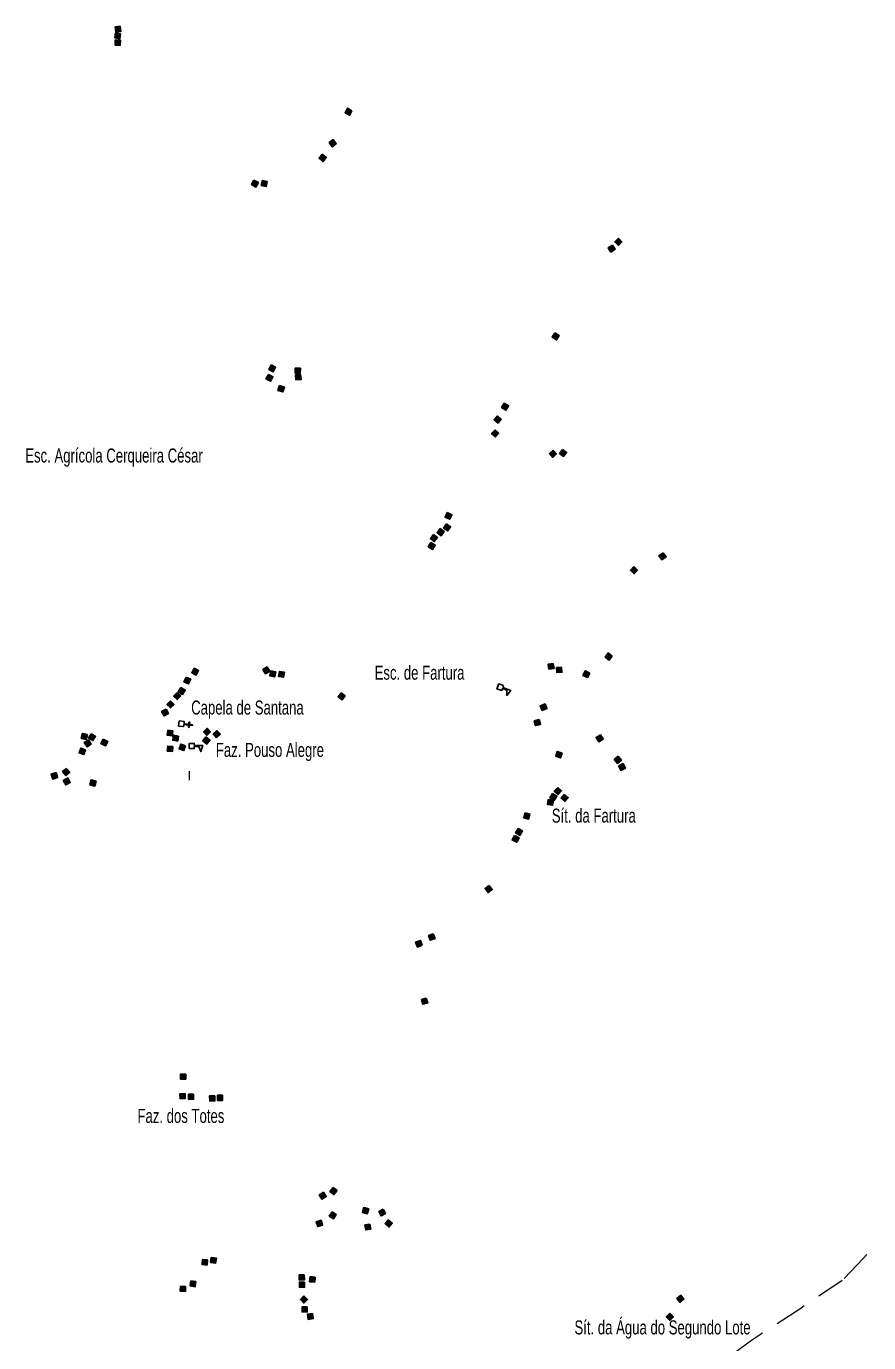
# Model space of a CAD drawing. Extents: x 679 to 705, y 7427.4 to 7455.4.
# Drawn here: x 688.04 to 692.84, y 7440 to 7447.5 of the extents above; entities that cross this region are included whole.
import ezdxf

# ---------------------------------------------------------------- set-up
doc = ezdxf.new("R2010")
doc.units = 0
doc.header["$LTSCALE"] = 0.032
doc.linetypes.add('DOT_DASHED', pattern=[7.7, 5, -1.2, 0.3, -1.2])
for name, color, linetype, lineweight in [('2', 7, 'Continuous', 25), ('4', 7, 'Continuous', 25), ('51', 7, 'Continuous', 13), ('56', 7, 'DOT_DASHED', 13), ('6', 7, 'Continuous', 25)]:
    doc.layers.add(name, color=color, linetype=linetype, lineweight=lineweight)
doc.layers.add('61', color=7, linetype='Continuous')

msp = doc.modelspace()

# ---------------------------------------------------------------- hatches: boundary and pattern name
at = {"layer": '2'}
for points in [[(688.5726, 7447.4971), (688.5764, 7447.4684), (688.5477, 7447.4646), (688.5438, 7447.4933)], [(688.5749, 7447.455), (688.5705, 7447.4263), (688.5418, 7447.4307), (688.5462, 7447.4594)], [(688.5734, 7447.4184), (688.5724, 7447.3894), (688.5434, 7447.3905), (688.5445, 7447.4195)], [(689.8928, 7447.0163), (689.8789, 7446.9909), (689.8535, 7447.0048), (689.8674, 7447.0302)], [(689.7627, 7446.8349), (689.7863, 7446.8517), (689.8031, 7446.828), (689.7795, 7446.8112)], [(689.7233, 7446.7681), (689.7462, 7446.7503), (689.7284, 7446.7274), (689.7055, 7446.7452)], [(689.3344, 7446.6207), (689.3599, 7446.6068), (689.346, 7446.5813), (689.3205, 7446.5952)], [(689.4106, 7446.6128), (689.4042, 7446.5845), (689.3759, 7446.5908), (689.3823, 7446.6191)], [(691.4108, 7446.2897), (691.4313, 7446.2692), (691.4108, 7446.2487), (691.3903, 7446.2692)], [(691.3764, 7446.2511), (691.3924, 7446.2269), (691.3682, 7446.2109), (691.3522, 7446.2351)], [(691.0483, 7445.751), (691.0733, 7445.7363), (691.0585, 7445.7113), (691.0336, 7445.726)], [(689.432, 7445.5688), (689.4578, 7445.5556), (689.4445, 7445.5297), (689.4187, 7445.543)], [(689.5989, 7445.5494), (689.5977, 7445.5204), (689.5688, 7445.5216), (689.57, 7445.5506)], [(689.4166, 7445.5147), (689.442, 7445.5007), (689.4279, 7445.4753), (689.4026, 7445.4893)], [(689.6004, 7445.5143), (689.6028, 7445.4854), (689.5738, 7445.4831), (689.5715, 7445.512)], [(689.4799, 7445.4509), (689.5076, 7445.4424), (689.4991, 7445.4147), (689.4714, 7445.4232)], [(690.7599, 7445.3504), (690.7849, 7445.3356), (690.7701, 7445.3106), (690.7452, 7445.3254)], [(690.7219, 7445.2776), (690.7438, 7445.2586), (690.7249, 7445.2367), (690.7029, 7445.2556)], [(690.7078, 7445.1994), (690.7295, 7445.1801), (690.7102, 7445.1585), (690.6885, 7445.1778)], [(691.0387, 7445.083), (691.0585, 7445.0618), (691.0372, 7445.042), (691.0175, 7445.0633)], [(691.0928, 7445.0876), (691.1159, 7445.0701), (691.0984, 7445.0469), (691.0753, 7445.0644)], [(690.4361, 7444.7276), (690.4623, 7444.7152), (690.45, 7444.689), (690.4237, 7444.7013)], [(690.4309, 7444.663), (690.455, 7444.6469), (690.4389, 7444.6227), (690.4148, 7444.6388)], [(690.3576, 7444.6026), (690.3802, 7444.5845), (690.3621, 7444.5619), (690.3395, 7444.58)], [(690.3952, 7444.636), (690.4185, 7444.6187), (690.4011, 7444.5955), (690.3779, 7444.6128)], [(690.3422, 7444.5574), (690.3671, 7444.5426), (690.3523, 7444.5177), (690.3274, 7444.5325)], [(691.6655, 7444.4981), (691.6824, 7444.4745), (691.6588, 7444.4576), (691.6419, 7444.4812)], [(691.4993, 7444.4201), (691.5202, 7444.4), (691.5001, 7444.3791), (691.4792, 7444.3992)], [(691.3761, 7443.9102), (691.3587, 7443.887), (691.3355, 7443.9044), (691.3529, 7443.9276)], [(688.9934, 7443.841), (689.0191, 7443.8275), (689.0055, 7443.8018), (688.9799, 7443.8154)], [(689.4102, 7443.8495), (689.4254, 7443.8248), (689.4007, 7443.8096), (689.3855, 7443.8343)], [(689.4304, 7443.826), (689.4587, 7443.8197), (689.4525, 7443.7914), (689.4241, 7443.7977)], [(689.5079, 7443.8179), (689.5027, 7443.7894), (689.4742, 7443.7946), (689.4793, 7443.8231)], [(691.0398, 7443.8686), (691.044, 7443.84), (691.0153, 7443.8357), (691.0111, 7443.8644)], [(691.0872, 7443.847), (691.0893, 7443.8181), (691.0603, 7443.816), (691.0582, 7443.8449)], [(691.2477, 7443.813), (691.2347, 7443.7871), (691.2088, 7443.8001), (691.2217, 7443.826)], [(688.9477, 7443.7896), (688.9741, 7443.7776), (688.9621, 7443.7512), (688.9357, 7443.7632)], [(688.8967, 7443.7032), (688.9176, 7443.683), (688.8975, 7443.6622), (688.8766, 7443.6823)], [(688.9182, 7443.7313), (688.9428, 7443.716), (688.9274, 7443.6914), (688.9029, 7443.7067)], [(689.8315, 7443.7014), (689.8544, 7443.6835), (689.8365, 7443.6607), (689.8136, 7443.6785)], [(688.8338, 7443.6084), (688.8479, 7443.5831), (688.8226, 7443.5689), (688.8085, 7443.5943)], [(688.8588, 7443.6553), (688.8793, 7443.6348), (688.8588, 7443.6143), (688.8383, 7443.6348)], [(690.9928, 7443.6379), (691.0036, 7443.611), (690.9766, 7443.6002), (690.9659, 7443.6271)], [(690.9599, 7443.5491), (690.9672, 7443.521), (690.9391, 7443.5137), (690.9319, 7443.5418)], [(688.3851, 7443.4629), (688.3784, 7443.4347), (688.3502, 7443.4413), (688.3568, 7443.4695)], [(688.4068, 7443.468), (688.4317, 7443.4531), (688.4168, 7443.4282), (688.3919, 7443.4431)], [(688.8727, 7443.4836), (688.8689, 7443.4549), (688.8402, 7443.4586), (688.8439, 7443.4874)], [(688.9047, 7443.4547), (688.9006, 7443.426), (688.8719, 7443.4302), (688.876, 7443.4589)], [(689.0604, 7443.4493), (689.0834, 7443.4316), (689.0656, 7443.4086), (689.0427, 7443.4264)], [(689.0873, 7443.4781), (689.0667, 7443.4578), (689.0463, 7443.4784), (689.067, 7443.4988)], [(689.1431, 7443.4644), (689.1215, 7443.4451), (689.1022, 7443.4667), (689.1238, 7443.486)], [(691.309, 7443.4617), (691.3236, 7443.4366), (691.2985, 7443.422), (691.2839, 7443.4471)], [(688.3748, 7443.3768), (688.3656, 7443.3493), (688.3381, 7443.3585), (688.3473, 7443.386)], [(688.3914, 7443.4332), (688.4075, 7443.4091), (688.3834, 7443.393), (688.3673, 7443.4171)], [(688.4759, 7443.4374), (688.5016, 7443.4239), (688.4882, 7443.3982), (688.4625, 7443.4116)], [(688.8721, 7443.395), (688.8696, 7443.3661), (688.8408, 7443.3685), (688.8432, 7443.3974)], [(688.9448, 7443.3992), (688.9357, 7443.3716), (688.9082, 7443.3808), (688.9173, 7443.4083)], [(691.0902, 7443.3579), (691.0814, 7443.3303), (691.0538, 7443.3391), (691.0626, 7443.3667)], [(691.409, 7443.3394), (691.4281, 7443.3175), (691.4062, 7443.2985), (691.3871, 7443.3204)], [(691.4115, 7443.2841), (691.4373, 7443.2972), (691.4505, 7443.2714), (691.4246, 7443.2583)], [(688.2067, 7443.2463), (688.2156, 7443.2187), (688.188, 7443.2098), (688.1791, 7443.2374)], [(688.2663, 7443.2706), (688.2852, 7443.2486), (688.2632, 7443.2297), (688.2443, 7443.2517)], [(688.2734, 7443.2157), (688.2874, 7443.1903), (688.262, 7443.1763), (688.248, 7443.2017)], [(688.4346, 7443.1977), (688.4277, 7443.1696), (688.3996, 7443.1764), (688.4064, 7443.2046)], [(691.0649, 7443.1621), (691.0867, 7443.143), (691.0676, 7443.1211), (691.0458, 7443.1402)], [(691.0115, 7443.0926), (691.0402, 7443.0886), (691.0362, 7443.0599), (691.0075, 7443.0639)], [(691.036, 7443.128), (691.0608, 7443.113), (691.0458, 7443.0882), (691.021, 7443.1032)], [(691.1027, 7443.1221), (691.1249, 7443.1035), (691.1063, 7443.0813), (691.0841, 7443.0999)], [(690.8789, 7443.0174), (690.9069, 7443.01), (690.8995, 7442.9819), (690.8715, 7442.9893)], [(690.8391, 7442.9285), (690.8641, 7442.9138), (690.8493, 7442.8888), (690.8244, 7442.9035)], [(690.8189, 7442.8883), (690.8447, 7442.875), (690.8314, 7442.8492), (690.8056, 7442.8626)], [(690.6745, 7442.6036), (690.6918, 7442.5803), (690.6686, 7442.563), (690.6513, 7442.5862)], [(690.3564, 7442.3283), (690.3664, 7442.3011), (690.3392, 7442.2911), (690.3292, 7442.3184)], [(690.2929, 7442.2629), (690.2657, 7442.2528), (690.2556, 7442.28), (690.2828, 7442.2901)], [(690.3163, 7441.9623), (690.3242, 7441.9344), (690.2963, 7441.9265), (690.2884, 7441.9544)], [(688.9455, 7441.5294), (688.9455, 7441.5004), (688.9165, 7441.5004), (688.9165, 7441.5294)], [(688.9419, 7441.4181), (688.9427, 7441.3891), (688.9137, 7441.3883), (688.9129, 7441.4172)], [(688.9895, 7441.415), (688.9907, 7441.3861), (688.9617, 7441.3849), (688.9606, 7441.4139)], [(689.1109, 7441.4053), (689.1117, 7441.3763), (689.0827, 7441.3756), (689.082, 7441.4045)], [(689.1559, 7441.4081), (689.1559, 7441.3791), (689.1269, 7441.3791), (689.1269, 7441.4081)], [(689.7316, 7440.8563), (689.7467, 7440.8316), (689.722, 7440.8164), (689.7069, 7440.8411)], [(689.7853, 7440.8837), (689.8081, 7440.8658), (689.7902, 7440.843), (689.7674, 7440.8609)], [(689.7792, 7440.7447), (689.8032, 7440.7284), (689.787, 7440.7044), (689.763, 7440.7206)], [(689.9881, 7440.7609), (689.9801, 7440.733), (689.9522, 7440.7409), (689.9602, 7440.7688)], [(690.0704, 7440.7603), (690.0845, 7440.735), (690.0591, 7440.7209), (690.0451, 7440.7463)], [(689.7168, 7440.6968), (689.7257, 7440.6692), (689.6981, 7440.6603), (689.6892, 7440.6879)], [(689.9949, 7440.6747), (690, 7440.6462), (689.9714, 7440.6411), (689.9663, 7440.6696)], [(690.1, 7440.6987), (690.1223, 7440.6801), (690.1037, 7440.6578), (690.0814, 7440.6764)], [(689.0702, 7440.4701), (689.0674, 7440.4413), (689.0385, 7440.4442), (689.0414, 7440.473)], [(689.1202, 7440.4807), (689.1161, 7440.452), (689.0874, 7440.4561), (689.0915, 7440.4848)], [(689.6208, 7440.3858), (689.6217, 7440.3568), (689.5927, 7440.3559), (689.5919, 7440.3849)], [(689.6828, 7440.3732), (689.6807, 7440.3443), (689.6518, 7440.3464), (689.6539, 7440.3753)], [(688.9453, 7440.3192), (688.9437, 7440.2902), (688.9147, 7440.2919), (688.9164, 7440.3208)], [(689.0038, 7440.3467), (688.9997, 7440.3179), (688.971, 7440.322), (688.9751, 7440.3508)], [(689.6229, 7440.3439), (689.6229, 7440.3149), (689.5939, 7440.3149), (689.5939, 7440.3439)], [(689.6195, 7440.2658), (689.64, 7440.2453), (689.6195, 7440.2248), (689.599, 7440.2453)], [(691.7662, 7440.2689), (691.7846, 7440.2466), (691.7623, 7440.2281), (691.7438, 7440.2505)], [(689.6384, 7440.2026), (689.6377, 7440.1736), (689.6087, 7440.1743), (689.6094, 7440.2033)], [(689.6679, 7440.1647), (689.6719, 7440.136), (689.6432, 7440.132), (689.6392, 7440.1608)], [(691.7037, 7440.1669), (691.7242, 7440.1464), (691.7037, 7440.1259), (691.6832, 7440.1464)]]:
    msp.add_hatch(color=256, dxfattribs=at).paths.add_polyline_path(points)

# ---------------------------------------------------------------- linework, layer by layer
for points in [[(688.5726, 7447.4971), (688.5764, 7447.4684), (688.5477, 7447.4646), (688.5438, 7447.4933)], [(688.5749, 7447.455), (688.5705, 7447.4263), (688.5418, 7447.4307), (688.5462, 7447.4594)], [(688.5734, 7447.4184), (688.5724, 7447.3894), (688.5434, 7447.3905), (688.5445, 7447.4195)], [(689.8928, 7447.0163), (689.8789, 7446.9909), (689.8535, 7447.0048), (689.8674, 7447.0302)], [(689.7627, 7446.8349), (689.7863, 7446.8517), (689.8031, 7446.828), (689.7795, 7446.8112)], [(689.7233, 7446.7681), (689.7462, 7446.7503), (689.7284, 7446.7274), (689.7055, 7446.7452)], [(689.3344, 7446.6207), (689.3599, 7446.6068), (689.346, 7446.5813), (689.3205, 7446.5952)], [(689.4106, 7446.6128), (689.4042, 7446.5845), (689.3759, 7446.5908), (689.3823, 7446.6191)], [(691.4108, 7446.2897), (691.4313, 7446.2692), (691.4108, 7446.2487), (691.3903, 7446.2692)], [(691.3764, 7446.2511), (691.3924, 7446.2269), (691.3682, 7446.2109), (691.3522, 7446.2351)], [(691.0483, 7445.751), (691.0733, 7445.7363), (691.0585, 7445.7113), (691.0336, 7445.726)], [(689.432, 7445.5688), (689.4578, 7445.5556), (689.4445, 7445.5297), (689.4187, 7445.543)], [(689.5989, 7445.5494), (689.5977, 7445.5204), (689.5688, 7445.5216), (689.57, 7445.5506)], [(689.4166, 7445.5147), (689.442, 7445.5007), (689.4279, 7445.4753), (689.4026, 7445.4893)], [(689.6004, 7445.5143), (689.6028, 7445.4854), (689.5738, 7445.4831), (689.5715, 7445.512)], [(689.4799, 7445.4509), (689.5076, 7445.4424), (689.4991, 7445.4147), (689.4714, 7445.4232)], [(690.7599, 7445.3504), (690.7849, 7445.3356), (690.7701, 7445.3106), (690.7452, 7445.3254)], [(690.7219, 7445.2776), (690.7438, 7445.2586), (690.7249, 7445.2367), (690.7029, 7445.2556)], [(690.7078, 7445.1994), (690.7295, 7445.1801), (690.7102, 7445.1585), (690.6885, 7445.1778)], [(691.0387, 7445.083), (691.0585, 7445.0618), (691.0372, 7445.042), (691.0175, 7445.0633)], [(691.0928, 7445.0876), (691.1159, 7445.0701), (691.0984, 7445.0469), (691.0753, 7445.0644)], [(690.4361, 7444.7276), (690.4623, 7444.7152), (690.45, 7444.689), (690.4237, 7444.7013)], [(690.4309, 7444.663), (690.455, 7444.6469), (690.4389, 7444.6227), (690.4148, 7444.6388)], [(690.3576, 7444.6026), (690.3802, 7444.5845), (690.3621, 7444.5619), (690.3395, 7444.58)], [(690.3952, 7444.636), (690.4185, 7444.6187), (690.4011, 7444.5955), (690.3779, 7444.6128)], [(690.3422, 7444.5574), (690.3671, 7444.5426), (690.3523, 7444.5177), (690.3274, 7444.5325)], [(691.6655, 7444.4981), (691.6824, 7444.4745), (691.6588, 7444.4576), (691.6419, 7444.4812)], [(691.4993, 7444.4201), (691.5202, 7444.4), (691.5001, 7444.3791), (691.4792, 7444.3992)], [(691.3761, 7443.9102), (691.3587, 7443.887), (691.3355, 7443.9044), (691.3529, 7443.9276)], [(688.9934, 7443.841), (689.0191, 7443.8275), (689.0055, 7443.8018), (688.9799, 7443.8154)], [(689.4102, 7443.8495), (689.4254, 7443.8248), (689.4007, 7443.8096), (689.3855, 7443.8343)], [(689.4304, 7443.826), (689.4587, 7443.8197), (689.4525, 7443.7914), (689.4241, 7443.7977)], [(689.5079, 7443.8179), (689.5027, 7443.7894), (689.4742, 7443.7946), (689.4793, 7443.8231)], [(691.0398, 7443.8686), (691.044, 7443.84), (691.0153, 7443.8357), (691.0111, 7443.8644)], [(691.0872, 7443.847), (691.0893, 7443.8181), (691.0603, 7443.816), (691.0582, 7443.8449)], [(691.2477, 7443.813), (691.2347, 7443.7871), (691.2088, 7443.8001), (691.2217, 7443.826)], [(688.9477, 7443.7896), (688.9741, 7443.7776), (688.9621, 7443.7512), (688.9357, 7443.7632)], [(688.8967, 7443.7032), (688.9176, 7443.683), (688.8975, 7443.6622), (688.8766, 7443.6823)], [(688.9182, 7443.7313), (688.9428, 7443.716), (688.9274, 7443.6914), (688.9029, 7443.7067)], [(689.8315, 7443.7014), (689.8544, 7443.6835), (689.8365, 7443.6607), (689.8136, 7443.6785)], [(688.8338, 7443.6084), (688.8479, 7443.5831), (688.8226, 7443.5689), (688.8085, 7443.5943)], [(688.8588, 7443.6553), (688.8793, 7443.6348), (688.8588, 7443.6143), (688.8383, 7443.6348)], [(690.9928, 7443.6379), (691.0036, 7443.611), (690.9766, 7443.6002), (690.9659, 7443.6271)], [(690.9599, 7443.5491), (690.9672, 7443.521), (690.9391, 7443.5137), (690.9319, 7443.5418)], [(688.3851, 7443.4629), (688.3784, 7443.4347), (688.3502, 7443.4413), (688.3568, 7443.4695)], [(688.4068, 7443.468), (688.4317, 7443.4531), (688.4168, 7443.4282), (688.3919, 7443.4431)], [(688.8727, 7443.4836), (688.8689, 7443.4549), (688.8402, 7443.4586), (688.8439, 7443.4874)], [(688.9047, 7443.4547), (688.9006, 7443.426), (688.8719, 7443.4302), (688.876, 7443.4589)], [(689.0604, 7443.4493), (689.0834, 7443.4316), (689.0656, 7443.4086), (689.0427, 7443.4264)], [(689.0873, 7443.4781), (689.0667, 7443.4578), (689.0463, 7443.4784), (689.067, 7443.4988)], [(689.1431, 7443.4644), (689.1215, 7443.4451), (689.1022, 7443.4667), (689.1238, 7443.486)], [(691.309, 7443.4617), (691.3236, 7443.4366), (691.2985, 7443.422), (691.2839, 7443.4471)], [(688.3748, 7443.3768), (688.3656, 7443.3493), (688.3381, 7443.3585), (688.3473, 7443.386)], [(688.3914, 7443.4332), (688.4075, 7443.4091), (688.3834, 7443.393), (688.3673, 7443.4171)], [(688.4759, 7443.4374), (688.5016, 7443.4239), (688.4882, 7443.3982), (688.4625, 7443.4116)], [(688.8721, 7443.395), (688.8696, 7443.3661), (688.8408, 7443.3685), (688.8432, 7443.3974)], [(688.9448, 7443.3992), (688.9357, 7443.3716), (688.9082, 7443.3808), (688.9173, 7443.4083)], [(691.0902, 7443.3579), (691.0814, 7443.3303), (691.0538, 7443.3391), (691.0626, 7443.3667)], [(691.409, 7443.3394), (691.4281, 7443.3175), (691.4062, 7443.2985), (691.3871, 7443.3204)], [(691.4115, 7443.2841), (691.4373, 7443.2972), (691.4505, 7443.2714), (691.4246, 7443.2583)], [(688.2067, 7443.2463), (688.2156, 7443.2187), (688.188, 7443.2098), (688.1791, 7443.2374)], [(688.2663, 7443.2706), (688.2852, 7443.2486), (688.2632, 7443.2297), (688.2443, 7443.2517)], [(688.2734, 7443.2157), (688.2874, 7443.1903), (688.262, 7443.1763), (688.248, 7443.2017)], [(688.4346, 7443.1977), (688.4277, 7443.1696), (688.3996, 7443.1764), (688.4064, 7443.2046)], [(691.0649, 7443.1621), (691.0867, 7443.143), (691.0676, 7443.1211), (691.0458, 7443.1402)], [(691.0115, 7443.0926), (691.0402, 7443.0886), (691.0362, 7443.0599), (691.0075, 7443.0639)], [(691.036, 7443.128), (691.0608, 7443.113), (691.0458, 7443.0882), (691.021, 7443.1032)], [(691.1027, 7443.1221), (691.1249, 7443.1035), (691.1063, 7443.0813), (691.0841, 7443.0999)], [(690.8789, 7443.0174), (690.9069, 7443.01), (690.8995, 7442.9819), (690.8715, 7442.9893)], [(690.8391, 7442.9285), (690.8641, 7442.9138), (690.8493, 7442.8888), (690.8244, 7442.9035)], [(690.8189, 7442.8883), (690.8447, 7442.875), (690.8314, 7442.8492), (690.8056, 7442.8626)], [(690.6745, 7442.6036), (690.6918, 7442.5803), (690.6686, 7442.563), (690.6513, 7442.5862)], [(690.3564, 7442.3283), (690.3664, 7442.3011), (690.3392, 7442.2911), (690.3292, 7442.3184)], [(690.2929, 7442.2629), (690.2657, 7442.2528), (690.2556, 7442.28), (690.2828, 7442.2901)], [(690.3163, 7441.9623), (690.3242, 7441.9344), (690.2963, 7441.9265), (690.2884, 7441.9544)], [(688.9455, 7441.5294), (688.9455, 7441.5004), (688.9165, 7441.5004), (688.9165, 7441.5294)], [(688.9419, 7441.4181), (688.9427, 7441.3891), (688.9137, 7441.3883), (688.9129, 7441.4172)], [(688.9895, 7441.415), (688.9907, 7441.3861), (688.9617, 7441.3849), (688.9606, 7441.4139)], [(689.1109, 7441.4053), (689.1117, 7441.3763), (689.0827, 7441.3756), (689.082, 7441.4045)], [(689.1559, 7441.4081), (689.1559, 7441.3791), (689.1269, 7441.3791), (689.1269, 7441.4081)], [(689.7316, 7440.8563), (689.7467, 7440.8316), (689.722, 7440.8164), (689.7069, 7440.8411)], [(689.7853, 7440.8837), (689.8081, 7440.8658), (689.7902, 7440.843), (689.7674, 7440.8609)], [(689.7792, 7440.7447), (689.8032, 7440.7284), (689.787, 7440.7044), (689.763, 7440.7206)], [(689.9881, 7440.7609), (689.9801, 7440.733), (689.9522, 7440.7409), (689.9602, 7440.7688)], [(690.0704, 7440.7603), (690.0845, 7440.735), (690.0591, 7440.7209), (690.0451, 7440.7463)], [(689.7168, 7440.6968), (689.7257, 7440.6692), (689.6981, 7440.6603), (689.6892, 7440.6879)], [(689.9949, 7440.6747), (690, 7440.6462), (689.9714, 7440.6411), (689.9663, 7440.6696)], [(690.1, 7440.6987), (690.1223, 7440.6801), (690.1037, 7440.6578), (690.0814, 7440.6764)], [(689.0702, 7440.4701), (689.0674, 7440.4413), (689.0385, 7440.4442), (689.0414, 7440.473)], [(689.1202, 7440.4807), (689.1161, 7440.452), (689.0874, 7440.4561), (689.0915, 7440.4848)], [(689.6208, 7440.3858), (689.6217, 7440.3568), (689.5927, 7440.3559), (689.5919, 7440.3849)], [(689.6828, 7440.3732), (689.6807, 7440.3443), (689.6518, 7440.3464), (689.6539, 7440.3753)], [(688.9453, 7440.3192), (688.9437, 7440.2902), (688.9147, 7440.2919), (688.9164, 7440.3208)], [(689.0038, 7440.3467), (688.9997, 7440.3179), (688.971, 7440.322), (688.9751, 7440.3508)], [(689.6229, 7440.3439), (689.6229, 7440.3149), (689.5939, 7440.3149), (689.5939, 7440.3439)], [(689.6195, 7440.2658), (689.64, 7440.2453), (689.6195, 7440.2248), (689.599, 7440.2453)], [(691.7662, 7440.2689), (691.7846, 7440.2466), (691.7623, 7440.2281), (691.7438, 7440.2505)], [(689.6384, 7440.2026), (689.6377, 7440.1736), (689.6087, 7440.1743), (689.6094, 7440.2033)], [(689.6679, 7440.1647), (689.6719, 7440.136), (689.6432, 7440.132), (689.6392, 7440.1608)], [(691.7037, 7440.1669), (691.7242, 7440.1464), (691.7037, 7440.1259), (691.6832, 7440.1464)]]:
    msp.add_lwpolyline(points, close=True, dxfattribs=at)
at = {"layer": '4'}
for points in [[(690.7502, 7443.7256), (690.746, 7443.7143), (690.7188, 7443.7243), (690.7288, 7443.7515), (690.756, 7443.7415), (690.7519, 7443.7302)], [(690.7519, 7443.7302), (690.7973, 7443.7135), (690.7747, 7443.6857), (690.7747, 7443.7166), (690.7502, 7443.7256)], [(688.9945, 7443.3953), (688.9945, 7443.3832), (688.9655, 7443.3832), (688.9655, 7443.4122), (688.9945, 7443.4122), (688.9945, 7443.4002)], [(688.9945, 7443.4002), (689.0429, 7443.4002), (689.0313, 7443.3663), (689.0206, 7443.3953), (688.9945, 7443.3953)]]:
    msp.add_lwpolyline(points, dxfattribs=at)
at = {"layer": '51'}
msp.add_line((688.9672, 7443.2034), (688.9675, 7443.2536), dxfattribs=at)
at = {"layer": '56'}
msp.add_lwpolyline([(697.8309, 7443.7554), (697.5731, 7443.6239), (697.3054, 7443.4844), (697.0473, 7443.3579), (696.7941, 7443.2281), (696.542, 7443.0961), (696.037, 7442.8424), (695.524, 7442.5825), (695.0163, 7442.3198), (694.7641, 7442.1893), (694.5164, 7442.0571), (694.2681, 7441.9019), (693.8232, 7441.5914), (693.7292, 7441.5206), (693.5456, 7441.3652), (693.3793, 7441.1375), (693.1926, 7440.9018), (693.0052, 7440.6906), (692.8076, 7440.4806), (692.6854, 7440.3538), (692.4502, 7440.1946), (692.1694, 7440.0116), (691.9405, 7439.8452)], dxfattribs=at)
at = {"layer": '6'}
for points in [[(688.9353, 7443.52), (688.9338, 7443.508), (688.9051, 7443.5116), (688.9087, 7443.5403), (688.9374, 7443.5367), (688.9359, 7443.5247)], [(688.9359, 7443.5247), (688.9628, 7443.5214), (688.9643, 7443.5334), (688.9692, 7443.5328), (688.9677, 7443.5208), (688.984, 7443.5187), (688.9834, 7443.514), (688.9671, 7443.516), (688.9656, 7443.504), (688.9607, 7443.5046), (688.9622, 7443.5166), (688.9353, 7443.52)]]:
    msp.add_lwpolyline(points, dxfattribs=at)

# ---------------------------------------------------------------- texts
at = {"layer": '61', "width": 0.7}
for s, p in [('Esc. Agrícola Cerqueira César', (688.0313, 7445.0125)), ('Esc. de Fartura', (690.022, 7443.7754)), ('Capela de Santana', (688.9767, 7443.5769)), ('Faz. Pouso Alegre', (689.1173, 7443.3357)), ('Sít. da Fartura', (691.0314, 7442.9613)), ('Faz. dos Totes', (688.6706, 7441.2508)), ('Sít. da Água do Segundo Lote', (691.1606, 7440.0462))]:
    msp.add_text(s, height=0.08, dxfattribs=at).set_placement(p)

doc.saveas('drawing.dxf')
